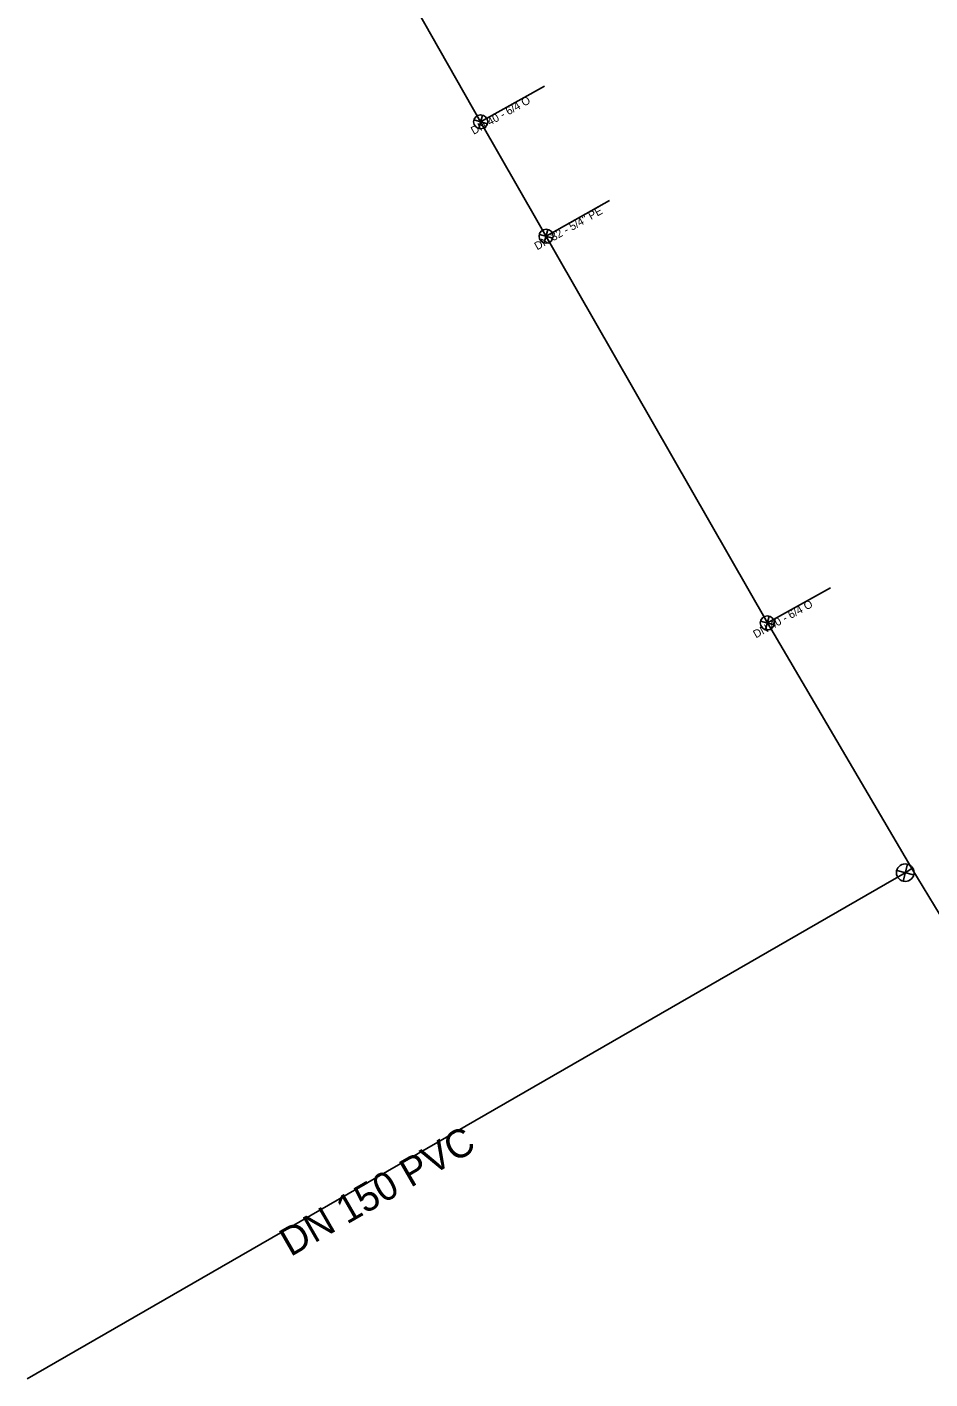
# Model space of a CAD drawing. Extents: x -443562 to -443270, y -1122830 to -1122511.
# Drawn here: x -443562.3 to -443511, y -1122669.3 to -1122592.4 of the extents above; entities that cross this region are included whole.
import ezdxf

# ---------------------------------------------------------------- set-up
doc = ezdxf.new("R2010")
doc.units = 0
for name, color, linetype in [('_pripojka_priblizne_', 7, 'Continuous'), ('_voda_smvak_prevzato_z_dokumentace_', 7, 'Continuous'), ('Default', 7, 'Continuous'), ('MoLevel 27', 7, 'Continuous'), ('MoLevel 32', 7, 'Continuous'), ('MoLevel 46', 7, 'Continuous'), ('MoLevel 53', 7, 'Continuous')]:
    doc.layers.add(name, color=color, linetype=linetype)

# ---------------------------------------------------------------- blocks, each defined once
blk = doc.blocks.new('_uzaver_')
at = {"layer": 'Default'}
for p, q in [((-0.000035, -0.000035), (0.000035, 0.000035)), ((0.000035, -0.000035), (-0.000035, 0.000035))]:
    blk.add_line(p, q, dxfattribs=at)
for radius in [0.00005, 0.0000025]:
    blk.add_circle((0, 0), radius, dxfattribs=at)
blk = doc.blocks.new('_uzaver_pripojka_')
at = {"layer": 'Default'}
for p, q in [((-0.000035, -0.000035), (0.000035, 0.000035)), ((0.000035, -0.000035), (-0.000035, 0.000035))]:
    blk.add_line(p, q, dxfattribs=at)
for radius in [0.00005, 0.0000025]:
    blk.add_circle((0, 0), radius, dxfattribs=at)

msp = doc.modelspace()

# ---------------------------------------------------------------- linework, layer by layer
at = {"layer": '_pripojka_priblizne_'}
for p, q in [((-443536.51, -1122597.8), (-443532.885, -1122595.766)), ((-443532.789, -1122604.303), (-443529.18, -1122602.27)), ((-443520.21, -1122626.29), (-443516.61, -1122624.29))]:
    msp.add_line(p, q, dxfattribs=at)
at = {"layer": '_voda_smvak_prevzato_z_dokumentace_'}
for p, q in [((-443512.37, -1122640.49), (-443562.299, -1122669.276)), ((-443511.998, -1122640.261), (-443512.37, -1122640.49)), ((-443511.998, -1122640.261), (-443509.735, -1122643.963))]:
    msp.add_line(p, q, dxfattribs=at)
msp.add_lwpolyline([(-443562.299, -1122552.41), (-443536.51, -1122597.8), (-443520.21, -1122626.29), (-443511.998, -1122640.261)], dxfattribs=at)

# ---------------------------------------------------------------- block references
at = {"layer": 'MoLevel 27', "xscale": 10000, "yscale": 10000, "rotation": -149.80982044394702}
msp.add_blockref('_uzaver_', (-443512.37, -1122640.49), dxfattribs=at)
at = {"layer": 'MoLevel 53', "xscale": 7999.999999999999}
for p, yscale, rotation in [((-443536.51, -1122597.8), 7999.999999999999, 29.291302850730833), ((-443532.789, -1122604.303), 7999.999999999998, 29.38813103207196), ((-443520.21, -1122626.29), 7999.999999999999, 29.054604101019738)]:
    msp.add_blockref('_uzaver_pripojka_', p, dxfattribs=dict(at, yscale=yscale, rotation=rotation))

# ---------------------------------------------------------------- texts
at = {"layer": 'MoLevel 32'}
for s, rotation, p in [('DN 40 - 6/4 O', 29.2913, (-443536.906, -1122598.544)), ("DN 32 - 5/4'' PE", 29.38813, (-443533.295, -1122605.11)), ('DN 40 - 6/4 O', 29.0546, (-443520.86, -1122627.172))]:
    msp.add_text(s, height=0.455, rotation=rotation, dxfattribs=at).set_placement(p)
at = {"layer": 'MoLevel 46'}
msp.add_text('DN 150 PVC', height=1.6049, rotation=29.96532, dxfattribs=at).set_placement((-443547.319, -1122662.353))

doc.saveas('drawing.dxf')
